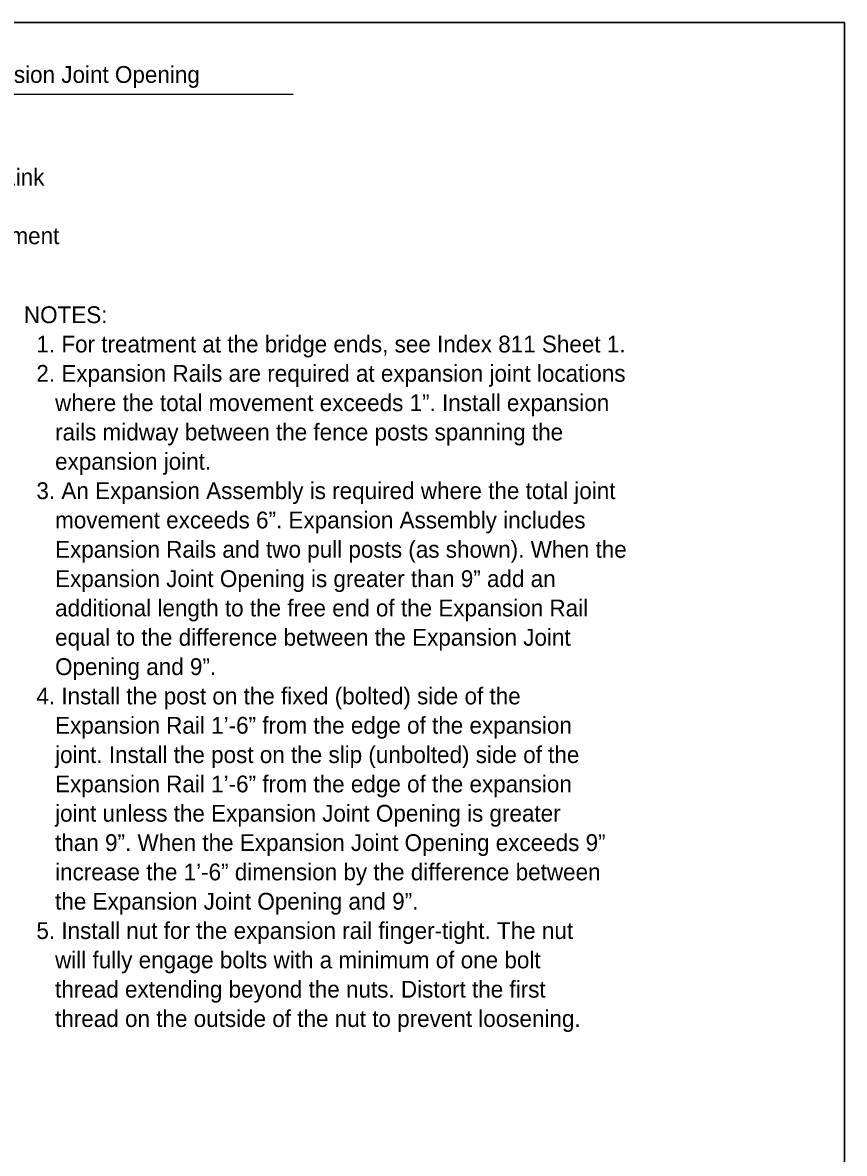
# Model space of a CAD drawing. Extents: x 0 to 41.1, y 0 to 25.9.
# Drawn here: x 31.18 to 41.05, y 12.37 to 25.95 of the extents above; entities that cross this region are included whole.
import ezdxf

# ---------------------------------------------------------------- set-up
doc = ezdxf.new("R2010")
doc.units = 0
for name, color, linetype in [('ActivePts-ConstElements', 7, 'Continuous'), ('Dimension', 7, 'Continuous'), ('Miscellaneous1', 7, 'Continuous'), ('TextStructures', 7, 'Continuous')]:
    doc.layers.add(name, color=color, linetype=linetype)

msp = doc.modelspace()

# ---------------------------------------------------------------- linework, layer by layer
at = {"layer": 'ActivePts-ConstElements'}
msp.add_lwpolyline([(0, 0), (41.051, 0), (41.051, 25.946), (0, 25.946)], close=True, dxfattribs=at)
at = {"layer": 'Dimension'}
msp.add_line((25.53, 25.088), (34.433, 25.088), dxfattribs=at)
at = {"layer": 'Miscellaneous1'}
msp.add_lwpolyline([(0, 25.946), (41.051, 25.946), (41.051, 0), (0, 0)], close=True, dxfattribs=at)

# ---------------------------------------------------------------- texts
at = {"layer": 'Dimension'}
for s, p in [('Bulge Chain Link ', (29.408, 23.991)), ('for joint movement', (29.408, 23.287)), ('NOTES:', (31.2, 22.339)), ('  1. For treatment at the bridge ends, see Index 811 Sheet 1.', (31.2, 21.987)), ('  2. Expansion Rails are required at expansion joint locations', (31.2, 21.635)), ('     where the total movement exceeds 1”. Install expansion', (31.2, 21.283)), ('     rails midway between the fence posts spanning the', (31.2, 20.931)), ('     expansion joint.  ', (31.2, 20.579)), ('  3. An Expansion Assembly is required where the total joint', (31.2, 20.227)), ('     movement exceeds 6”. Expansion Assembly includes', (31.2, 19.875)), ('     Expansion Rails and two pull posts (as shown). When the', (31.2, 19.523)), ('     Expansion Joint Opening is greater than 9” add an', (31.2, 19.171)), ('     additional length to the free end of the Expansion Rail', (31.2, 18.819)), ('     equal to the difference between the Expansion Joint', (31.2, 18.467)), ('     Opening and 9”. ', (31.2, 18.115)), ('  4. Install the post on the fixed (bolted) side of the', (31.2, 17.763)), ('     Expansion Rail 1’-6” from the edge of the expansion', (31.2, 17.411)), ('     joint. Install the post on the slip (unbolted) side of the', (31.2, 17.059)), ('     Expansion Rail 1’-6” from the edge of the expansion', (31.2, 16.707)), ('     joint unless the Expansion Joint Opening is greater', (31.2, 16.355)), ('     than 9”. When the Expansion Joint Opening exceeds 9”', (31.2, 16.003)), ('     increase the 1’-6” dimension by the difference between', (31.2, 15.651)), ('     the Expansion Joint Opening and 9”. ', (31.2, 15.299)), ('  5. Install nut for the expansion rail finger-tight. The nut', (31.2, 14.947)), ('     will fully engage bolts with a minimum of one bolt', (31.2, 14.595)), ('     thread extending beyond the nuts. Distort the first', (31.2, 14.243)), ('     thread on the outside of the nut to prevent loosening.   ', (31.2, 13.891))]:
    msp.add_text(s, height=0.2016, dxfattribs=at).set_placement(p)
at = {"layer": 'TextStructures'}
msp.add_text('3\'-0" (Min.) + Expansion Joint Opening', height=0.2016, dxfattribs=at).set_placement((28.707, 25.223))

doc.saveas('drawing.dxf')
